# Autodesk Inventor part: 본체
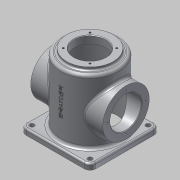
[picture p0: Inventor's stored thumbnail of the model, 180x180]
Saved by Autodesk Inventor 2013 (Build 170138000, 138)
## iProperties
Created: 2015-10
Part Number: 본체
Material: 알루미늄 6061
Document SubType Name: Modeling
Designer: Administrator
Density: 2.71 g/cm^3
Mass: 987.032 g
Surface Area: 1039.63 cm^2
Volume: 364.218 cm^3
Author: Administrator
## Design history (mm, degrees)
sketch "스케치1"
  geometry: L1 (-60, 60)-(60, 60); L2 (60, 60)-(60, -60); L3 (60, -60)-(-60, -60); L4 (-60, -60)-(-60, 60); 1 further point
  constraints: 8 end point, 2 parallel, 1 horizontal, 1 perpendicular
  dimensions: "d0" = 120 distance between parallel lines of L3 L1; "d2" = 120 distance between parallel lines of L2 L4; "d3" = 60 distance from line of point (0, 0) L1; "d4" = 60 distance from line of point (0, 0) L4
extrude "돌출1" new body sketch "스케치1" distance "d5" = 10; taper "d6" = 0 deg
sketch "스케치2"
  geometry: C1 r 50 at (0, 0); 1 further point
  constraints: 1 centre point, 1 coincident
  dimensions: "d7" = 100 diameter of C1
extrude "돌출2" join sketch "스케치2" distance "d9" = 110; taper "d10" = 0 deg
sketch "스케치3"
  geometry: C1 r 50 at (0, 0) reference; C2 r 40 at (0, 0)
  constraints: 1 centre point, 1 coincident
  dimensions: "d11" = 80 diameter of C2
extrude "돌출3" join sketch "스케치3" distance "d13" = 5; taper "d14" = 0 deg
sketch "스케치4"
  geometry: C1 r 50 at (0, 0) reference; C2 r 4 at (-50, 50); C3 r 4 at (50, 50); C4 r 4 at (50, -50); C5 r 4 at (-50, -50)
  constraints: 4 centre point
  dimensions: "d15" = 8 diameter of C2; "d17" = 8 diameter of C3; "d18" = 8 diameter of C4; "d19" = 8 diameter of C5; "d20" = 100 distance of C3.centre C2.centre; "d21" = 50 horizontal distance of C1.centre C2.centre; "d22" = 100 distance of C4.centre C3.centre; "d23" = 50 horizontal distance of C1.centre C3.centre; "d24" = 100 distance of C5.centre C4.centre; "d25" = 50 horizontal distance of C1.centre C4.centre; "d26" = 100 distance of C2.centre C5.centre; "d27" = 50 horizontal distance of C1.centre C2.centre
extrude "돌출4" cut sketch "스케치4" stored distance "d28" = 5; taper "d29" = 0 deg
node "작업 평면1"
sketch "스케치5"
  geometry: C1 r 40 at (0, 60); 1 further point
  constraints: 1 centre point
  dimensions: "d31" = 80 diameter of C1; "d33" = 60 distance of point (0, 0) C1.centre; "d34" = 0 horizontal distance of point (0, 0) C1.centre
extrude "돌출5" join sketch "스케치5" stored distance "d35" = 5; taper "d36" = 0 deg
node "작업 평면2"
sketch "스케치6"
  geometry: C1 r 40 at (0, 60); 1 further point
  constraints: 1 centre point
  dimensions: "d38" = 80 diameter of C1; "d40" = 60 distance of point (0, 0) C1.centre; "d41" = 0 horizontal distance of point (0, 0) C1.centre
extrude "돌출6" join sketch "스케치6" stored distance "d42" = 5; taper "d43" = 0 deg
sketch "스케치7"
  geometry: C1 r 45 at (0, 0); 1 further point
  constraints: 1 centre point, 1 coincident
  dimensions: "d44" = 90 diameter of C1
extrude "돌출7" cut sketch "스케치7" distance "d46" = 112; taper "d47" = 0 deg
sketch "스케치8"
  geometry: C1 r 40 at (0, 0) reference; C2 r 27 at (0, 0)
  constraints: 1 centre point, 1 coincident
  dimensions: "d48" = 54 diameter of C2
extrude "돌출8" cut sketch "스케치8" stored distance "d50" = 112; taper "d51" = 0 deg
sketch "스케치9"
  geometry: C1 r 40 at (0, 0) reference; C2 r 27 at (0, 0); 1 further point
  constraints: 1 centre point, 1 coincident
  dimensions: "d52" = 54 diameter of C2
extrude "돌출9" cut sketch "스케치9" stored distance "d54" = 112; taper "d55" = 0 deg
sketch "스케치10"
  geometry: C1 r 40 at (0, 0) reference; C2 r 27 at (0, 0); 1 further point
  constraints: 1 centre point, 1 coincident
  dimensions: "d56" = 54 diameter of C2
extrude "돌출10" cut sketch "스케치10" stored distance "d58" = 112; taper "d59" = 0 deg
sketch "스케치11" dims "d60" = 65
  geometry: L1 (0, 0)-(0, 32.5); C1 r 40 at (0, 0) reference; C2 r 2 at (0, 32.5); 1 further point
  constraints: 2 coincident, 2 end point, 1 centre point, 1 vertical, 1 vertical alignment, 2 other
  dimensions: "d62" = 4 diameter of C2
hole "구멍1" sketch "스케치11" at (0, 32.5) diameter "d63" = 3.242; stored, may be unused: countersink angle "d67" = 90 deg, drill point angle "d69" = 118 deg; dims "d64" = 8, "d65" = 4, "d66" = 2, "d68" = 10
sketch "스케치12" dims "d73" = 65
  geometry: L1 (0, 0)-(0, 32.5); C1 r 40 at (0, 0) reference; C2 r 2 at (0, 32.5); 1 further point
  constraints: 2 coincident, 2 end point, 1 centre point, 1 vertical, 1 vertical alignment, 2 other
  dimensions: "d75" = 4 diameter of C2
hole "구멍2" sketch "스케치12" at (0, 32.5) diameter "d76" = 3.242; stored, may be unused: countersink angle "d80" = 90 deg, drill point angle "d82" = 118 deg; dims "d77" = 8, "d78" = 4, "d79" = 2, "d81" = 10
sketch "스케치13"
  geometry: L1 (0, 0)-(0, 32.5); L2 (0, 0)-(22.981, 22.981); C1 r 40 at (0, 0) reference; C2 r 2 at (22.981, 22.981); A1 r 32.5 centre (0, 0) between (0, 32.5) and (22.981, 22.981)
  constraints: 4 end point, 2 centre point, 2 coincident, 2 point on circle, 1 vertical
  dimensions: "d86" = 65 diameter of A1; "d88" = 45 deg angle of L2 L1; "d90" = 4 diameter of C2
hole "구멍3" sketch "스케치13" at (22.981, 22.981) diameter "d91" = 3.242; stored, may be unused: countersink angle "d95" = 90 deg, drill point angle "d97" = 118 deg; dims "d92" = 8, "d93" = 4, "d94" = 2, "d96" = 10
node "작업 평면3"
sketch "스케치14"
  geometry: L1 (-3.602, 45.113)-(-3.602, 94.887); L2 (-3.602, 94.887)-(3.602, 94.887); L3 (3.602, 94.887)-(3.602, 45.113); L4 (3.602, 45.113)-(-3.602, 45.113); L5 (0, 45.113)-(0, 94.887); L6 (-3.602, 70)-(3.602, 70); 1 further point
  constraints: 4 end point, 4 midpoint, 2 other
  dimensions: "d104" = 0 distance from line of point (0, 0) L5; "d105" = 70 distance from line of point (0, 0) L6
feature "엠보싱1" sketch "스케치14" dims "d0" = 120, "d2" = 120, "d3" = 60, "d4" = 60, "d15" = 8, "d17" = 8, "d18" = 8, "d19" = 8, "d20" = 100, "d21" = 50, "d22" = 100, "d23" = 50, "d24" = 100, "d25" = 50, "d26" = 100, "d27" = 50, "d106" = 0.5, "d107" = 0
fillet "모깎기1" dims "d108" = 10
fillet "모깎기2" dims "d109" = 5
fillet "모깎기3" dims "d110" = 5
chamfer "모따기1" distance "d111" = 3; stored, may be unused: second distance "d112" = 2, angle "d113" = 45 deg
chamfer "모따기2" distance "d114" = 1; stored, may be unused: second distance "d115" = 2, angle "d116" = 45 deg
fillet "모깎기4" dims "d117" = 3
fillet "모깎기5" dims "d118" = 5
fillet "모깎기6" dims "d119" = 3
node "솔리드1"
pattern_circular "원형 패턴1" dims angle "d71" = 360 deg
pattern_circular "원형 패턴2" dims angle "d84" = 360 deg
pattern_circular "원형 패턴3" dims angle "d99" = 360 deg
other parameters: "d30" = 62, "d37" = -62, "d101" = -53.75
